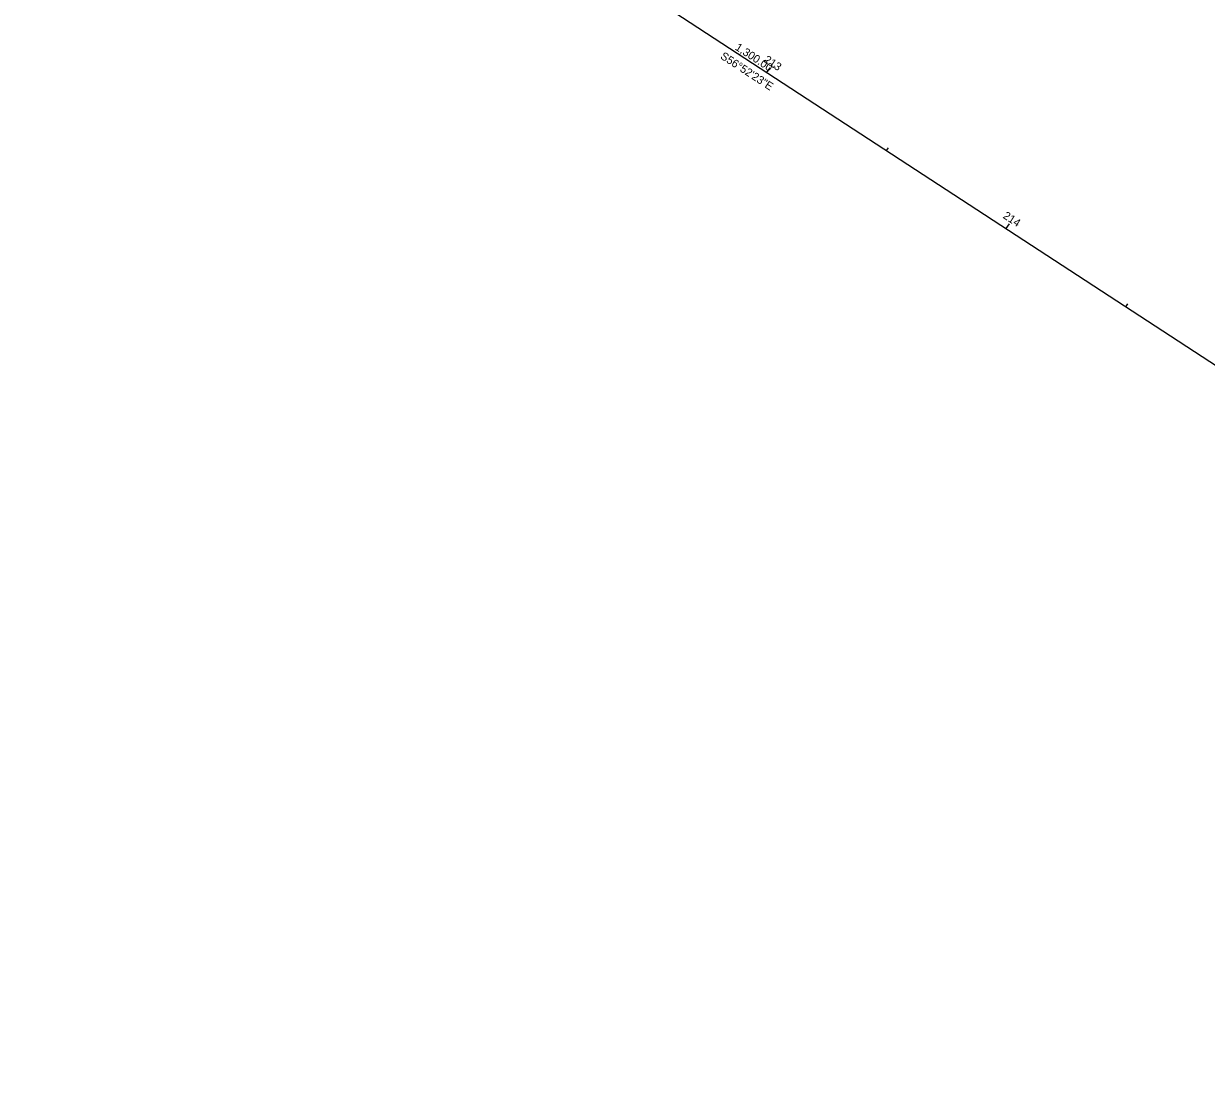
# Model space of a CAD drawing. Extents: x 1323137 to 1326838, y 458936 to 461644.
# Drawn here: x 1326010.6 to 1326424.4, y 458936.6 to 459305.6 of the extents above; entities that cross this region are included whole.
import ezdxf

# ---------------------------------------------------------------- set-up
doc = ezdxf.new("R2010")
doc.units = 0
for name, color, linetype in [('CM_Corridor_Range_Final', 7, 'Continuous'), ('Default', 7, 'Continuous'), ('DR_P_Ditch', 7, 'Continuous'), ('RD_P_GR_Rt', 7, 'Continuous'), ('SG_P_Wiring', 7, 'Continuous'), ('SN_P_Signs', 7, 'Continuous'), ('SN_X_Public', 7, 'Continuous'), ('UT_X_Electric_Cells', 7, 'Continuous')]:
    doc.layers.add(name, color=color, linetype=linetype)

msp = doc.modelspace()

# ---------------------------------------------------------------- linework, layer by layer
at = {"layer": 'CM_Corridor_Range_Final'}
for p, q in [((1326270.66, 459288.55), (1326271.76, 459290.22)), ((1326312.54, 459261.22), (1326313.19, 459262.23)), ((1326354.41, 459233.9), (1326355.5, 459235.57)), ((1326396.28, 459206.57), (1326396.94, 459207.58))]:
    msp.add_line(p, q, dxfattribs=at)
at = {"layer": 'Default'}
msp.add_line((1325721.36, 459647), (1326810.06, 458936.55), dxfattribs=at)
at = {"layer": 'SN_P_Signs'}
for p in [(1325721.36, 459647), (1326140.09, 459373.75)]:
    msp.add_line(p, (1326810.06, 458936.55), dxfattribs=at)
at = {"layer": 'SN_X_Public'}
for p, q in [((1326270.66, 459288.55), (1326271.32, 459289.55)), ((1326354.41, 459233.9), (1326355.06, 459234.9))]:
    msp.add_line(p, q, dxfattribs=at)

# ---------------------------------------------------------------- texts
at = {"layer": 'CM_Corridor_Range_Final'}
for s, p in [('213', (1326269.35, 459292.39)), ('214', (1326353.03, 459237.78))]:
    msp.add_text(s, height=2.8, rotation=326.873, dxfattribs=at).set_placement(p)
at = {"layer": 'DR_P_Ditch'}
msp.add_text("1,300.00'", height=2.8, rotation=326.873, dxfattribs=at).set_placement((1326259.28, 459296.72))
at = {"layer": 'RD_P_GR_Rt'}
msp.add_text('S56°52\'23"E', height=2.8, rotation=326.873, dxfattribs=at).set_placement((1326254.12, 459293.61))
at = {"layer": 'SG_P_Wiring'}
msp.add_text('S56°52\'23"E', height=2.8, rotation=326.873, dxfattribs=at).set_placement((1326254.12, 459293.61))
at = {"layer": 'UT_X_Electric_Cells'}
msp.add_text("1,300.00'", height=2.8, rotation=326.873, dxfattribs=at).set_placement((1326259.28, 459296.72))

doc.saveas('drawing.dxf')
